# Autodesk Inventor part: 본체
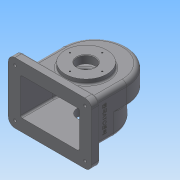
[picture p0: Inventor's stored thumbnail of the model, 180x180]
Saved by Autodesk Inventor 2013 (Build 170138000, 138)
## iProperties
Created: 2017-11
Part Number: 본체
Material: 일반
Document SubType Name: Modeling
Designer: Administrator
Density: 1 g/cm^3
Author: Administrator
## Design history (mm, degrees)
sketch "스케치2"
  geometry: L1 (-58, 0)-(58, 0); L2 (58, 0)-(58, -65); L3 (58, -65)-(-58, -65); L4 (-58, -65)-(-58, 0); L5 (-58, 0)-(58, -65); L6 (58, 0)-(-58, -65); C1 r 58 at (0, 0); 3 further points
  constraints: 12 end point, 3 midpoint, 2 coincident, 2 parallel, 1 centre point, 1 horizontal, 1 perpendicular
  dimensions: "d0" = 116 diameter of C1; "d2" = 65 distance of L1.end L2.end; "d3" = 116 distance of L1.start L1.end
extrude "돌출1" new body sketch "스케치2" stored distance "d4" = 38; taper "d5" = 0 deg
sketch "스케치3"
  geometry: L1 (-58, -65)-(58, -65) reference; L2 (-58, -23)-(58, -23); L3 (58, -23)-(58, -65); L4 (58, -65)-(-58, -65); L5 (-58, -65)-(-58, -23); L6 (-58, -23)-(58, -65); L7 (58, -23)-(-58, -65); A1 r 58 centre (0, -23) between (40, -65) and (-40, -65); 2 further points
  constraints: 12 end point, 5 midpoint, 2 parallel, 2 point on circle, 2 point on line, 1 centre point, 1 horizontal, 1 perpendicular
  dimensions: "d6" = 42 distance of L2.end L3.end; "d8" = 116 distance of L2.start L2.end; "d9" = 116 diameter of A1
extrude "돌출2" join sketch "스케치3" distance "d10" = 38; taper "d11" = 0 deg
feature "쉘1" dims "d12" = 5
sketch "스케치5"
  geometry: L1 (111, -5)-(111, -71) reference; L2 (111, -71)-(5, -71) reference; L3 (5, -71)-(5, -5) reference; L4 (5, -5)-(111, -5) reference; L5 (116, 0)-(116, -76) reference; L6 (0, 0)-(0, -76) reference; L7 (0, -38)-(116, -38); L8 (-17, 17)-(133, 17); L9 (133, 17)-(133, -93); L10 (133, -93)-(-17, -93); L11 (-17, -93)-(-17, 17); L12 (-17, 17)-(133, -93); L13 (133, 17)-(-17, -93); 2 further points
  constraints: 14 end point, 5 midpoint, 2 parallel, 1 horizontal, 1 perpendicular
  dimensions: "d13" = 150 distance of L9.end L10.end; "d15" = 110 distance of L8.end L9.end
extrude "돌출3" join sketch "스케치5" distance "d16" = 15; taper "d17" = 0 deg
sketch "스케치6"
  geometry: L1 (75, -80)-(-75, -80) reference; C1 r 37.5 at (0, -15); 1 further point
  constraints: 1 centre point, 1 midpoint, 1 vertical alignment
  dimensions: "d18" = 75 diameter of C1; "d19" = 65 distance from line of L1 C1.centre
extrude "돌출4" join sketch "스케치6" distance "d20" = 9; taper "d21" = 0 deg
sketch "스케치7"
  geometry: L1 (75, -80)-(-75, -80) reference; C1 r 31 at (0, -15); 2 further points
  constraints: 1 centre point, 1 midpoint, 1 vertical alignment
  dimensions: "d22" = 62 diameter of C1; "d24" = 65 distance from line of L1 C1.centre
extrude "돌출5" join sketch "스케치7" distance "d25" = 10; taper "d26" = 0 deg
sketch "스케치8"
  geometry: C1 r 37.5 at (0, 0) reference; C2 r 16 at (0, 0); 1 further point
  constraints: 1 centre point, 1 coincident
  dimensions: "d27" = 32 diameter of C2
extrude "돌출6" cut sketch "스케치8" stored distance "d28" = 10; taper "d29" = 0 deg
node "작업 평면1"
sketch "스케치9"
  geometry: L1 (0, 0)-(-116, 0) reference; C1 r 6 at (-58, -19); 2 further points
  constraints: 1 centre point, 1 midpoint, 1 vertical alignment
  dimensions: "d31" = 12 diameter of C1; "d32" = 19 distance from line of L1 C1.centre
extrude "돌출7" join sketch "스케치9" stored distance "d33" = 10; taper "d34" = 0 deg
sketch "스케치10"
  geometry: C1 r 6 at (0, 0) reference
hole "구멍1" sketch "스케치10" at (0, 0) diameter "d35" = 4.459; stored, may be unused: countersink angle "d39" = 90 deg, drill point angle "d41" = 118 deg; dims "d36" = 6, "d37" = 4, "d38" = 2, "d40" = 8
sketch "스케치11"
  geometry: C1 r 16 at (0, 0) reference; 2 further points
  constraints: 1 vertical alignment
  dimensions: "d42" = 29 distance of C1.centre point (0, 29)
hole "구멍2" sketch "스케치11" at (0, 29) diameter "d43" = 2.459; stored, may be unused: countersink angle "d47" = 90 deg, drill point angle "d49" = 118 deg; dims "d44" = 6, "d45" = 4, "d46" = 2, "d48" = 8
sketch "스케치12"
  geometry: C1 r 16 at (0, 0) reference; 2 further points
  constraints: 1 vertical alignment
  dimensions: "d53" = 26 distance of C1.centre point (0, 26)
hole "구멍3" sketch "스케치12" at (0, 26) diameter "d54" = 2.459; stored, may be unused: countersink angle "d58" = 90 deg, drill point angle "d60" = 118 deg; dims "d55" = 6, "d56" = 4, "d57" = 2, "d59" = 8
fillet "모깎기1" dims "d64" = 12
sketch "스케치14"
  geometry: A1 r 12 centre (-5, -5) between (-17, -5) and (-5, -17) reference; 1 further point
hole "구멍4" sketch "스케치14" at (-5, -5) diameter "d65" = 5; stored, may be unused: countersink angle "d69" = 90 deg, drill point angle "d71" = 118 deg; dims "d66" = 5, "d67" = 12, "d68" = 5, "d70" = 8
sketch "스케치15"
  geometry: A1 r 12 centre (-5, 81) between (-5, 93) and (-17, 81) reference; A2 r 12 centre (121, 81) between (133, 81) and (121, 93) reference; 1 further point
hole "구멍5" sketch "스케치15" at (-5, 81), (121, 81) diameter "d72" = 5; stored, may be unused: countersink angle "d76" = 90 deg, drill point angle "d78" = 118 deg; dims "d73" = 5, "d74" = 12, "d75" = 5, "d77" = 8
sketch "스케치16"
  geometry: L1 (0, -65)-(0, 0) reference; L2 (81, -80)-(-5, -80) reference; L3 (-5, -65)-(81, -65) reference; 2 further points
  constraints: 1 other
  dimensions: "d79" = 40 distance from line of L2 point (38, -40); "d80" = 38 distance from line of point (38, -40) L1
feature "엠보싱1" sketch "스케치16" dims "d81" = 0.5, "d82" = 0
fillet "모깎기2" dims "d83" = 3
fillet "모깎기3" dims "d84" = 3
fillet "모깎기4" dims "d85" = 8
chamfer "모따기1" distance "d86" = 1; stored, may be unused: second distance "d87" = 2, angle "d88" = 45 deg
fillet "모깎기5" dims "d89" = 3
fillet "모깎기6" dims "d90" = 3
fillet "모깎기7" dims "d91" = 3
node "솔리드1"
pattern_circular "원형 패턴1" dims angle "d51" = 360 deg
pattern_circular "원형 패턴2" dims angle "d62" = 360 deg
mirror "대칭1"
other parameters: "d30" = -144
